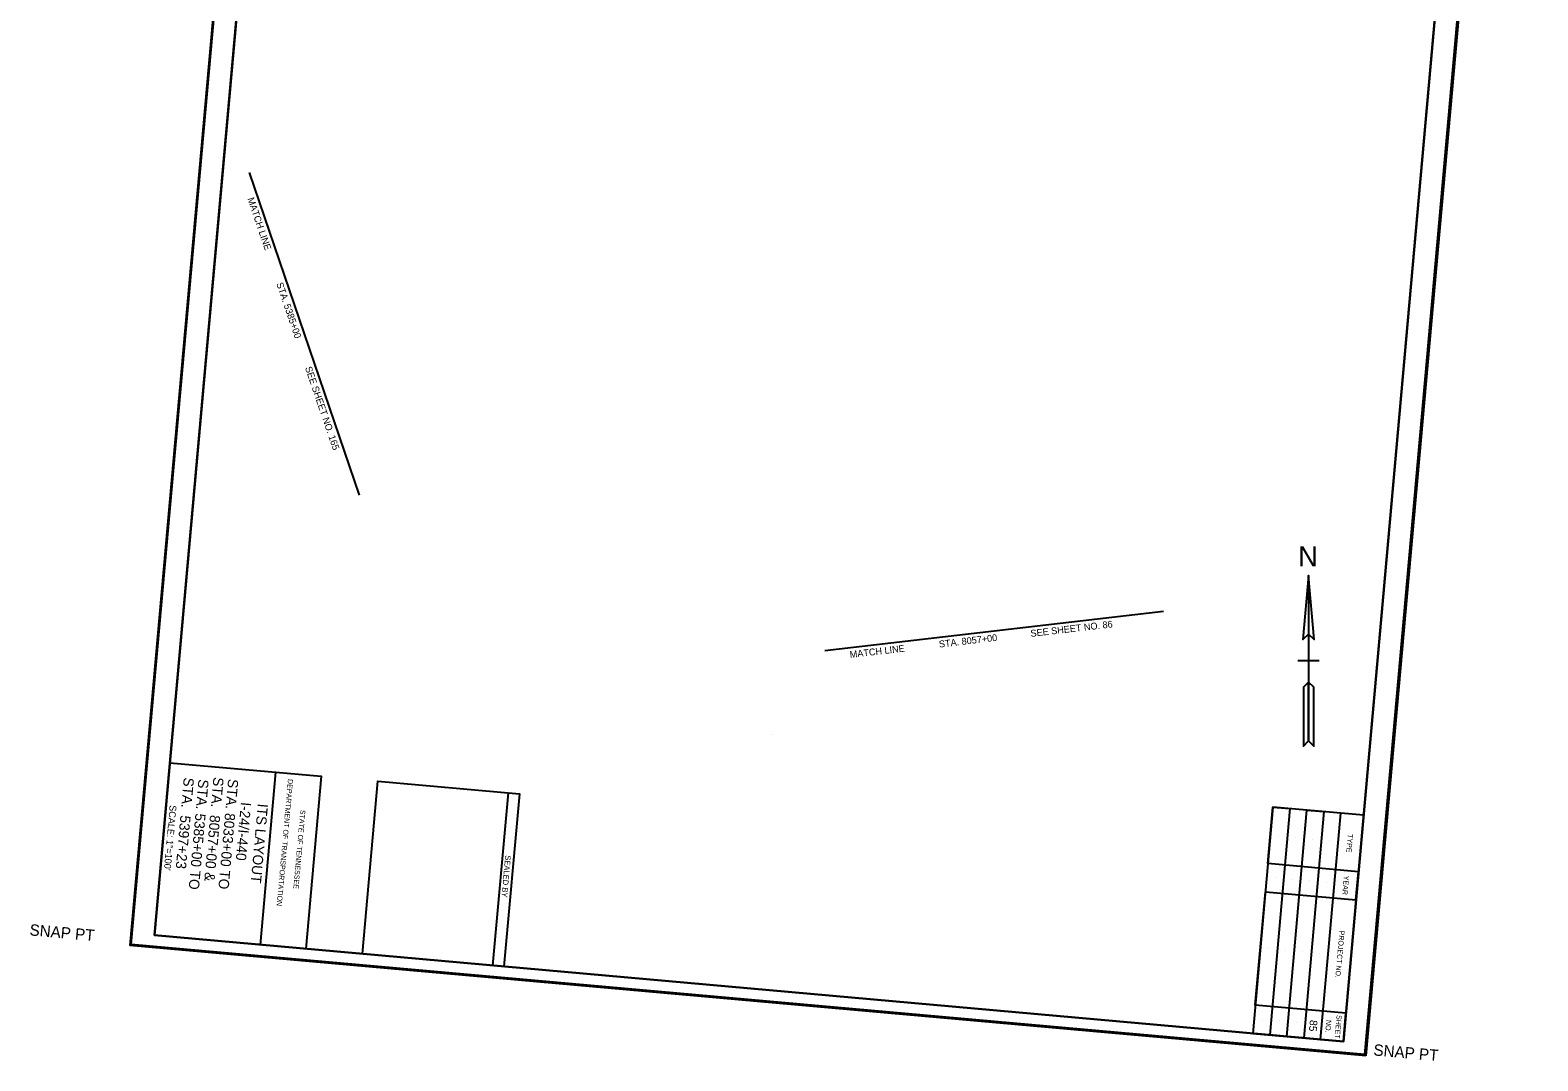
# Model space of a CAD drawing. Extents: x 1751939 to 1754719, y 651993 to 655620.
# Drawn here: x 1751939 to 1754592, y 651993 to 653806 of the extents above; entities that cross this region are included whole.
import ezdxf

# ---------------------------------------------------------------- set-up
doc = ezdxf.new("R2010")
doc.units = 0
for name, color, linetype in [('DESIGN - CENTERLINE - Proposed Text', 7, 'Continuous'), ('DESIGN - SCRATCH - User 1', 7, 'Continuous'), ('DESIGN - SHEET - Corner Text', 7, 'Continuous'), ('DESIGN - SHEET - Linework', 7, 'Continuous'), ('DESIGN - SHEET - Plot Shape', 7, 'Continuous'), ('ITS - CONST TEXT', 7, 'Continuous'), ('ITS - EXISTING COMM CABLE', 7, 'Continuous'), ('ITS - EXISTING HAR', 7, 'Continuous')]:
    doc.layers.add(name, color=color, linetype=linetype)

msp = doc.modelspace()

# ---------------------------------------------------------------- linework, layer by layer
at = {"layer": 'DESIGN - CENTERLINE - Proposed Text'}
for p, q in [((1754188.3, 652696.6), (1754169.4, 652696.6)), ((1754207.2, 652696.6), (1754188.3, 652696.6))]:
    msp.add_line(p, q, dxfattribs=at)
msp.add_lwpolyline([(1754188.3, 652846.6), (1754178.5, 652734), (1754188.3, 652743.8), (1754198.1, 652734), (1754188.3, 652846.6), (1754188.3, 652555.7), (1754197.4, 652546.6), (1754197.4, 652650.1), (1754188.3, 652659.2), (1754179.2, 652650.1), (1754179.2, 652546.6), (1754188.3, 652555.7)], dxfattribs=at)
for points in [[(1754188.3, 652743.8), (1754198.1, 652734), (1754188.3, 652846.6)], [(1754179.2, 652546.6), (1754188.3, 652555.7), (1754188.3, 652659.2), (1754179.2, 652650.1)]]:
    msp.add_lwpolyline(points, close=True, dxfattribs=at)
at = {"layer": 'DESIGN - SCRATCH - User 1'}
for p, q in [((1753243.6, 652566.8), (1753243.6, 652566.8)), ((1754136.2, 652388.3), (1754136.2, 652388.3)), ((1754136.2, 652388.3), (1754136.2, 652388.3)), ((1754136.2, 652388.3), (1754136.2, 652388.3)), ((1754136.2, 652388.3), (1754136.2, 652388.3)), ((1754166.1, 652385.6), (1754166.1, 652385.6)), ((1754166.1, 652385.6), (1754166.1, 652385.6)), ((1754166.1, 652385.6), (1754166.1, 652385.6)), ((1754196, 652383), (1754196, 652383)), ((1754196, 652383), (1754196, 652383)), ((1754225.8, 652380.3), (1754225.8, 652380.3)), ((1752264.5, 652357.1), (1752264.5, 652357.1)), ((1752264.5, 652357.1), (1752264.5, 652357.1)), ((1752264.6, 652357.2), (1752264.6, 652357.2)), ((1754129.6, 652314.6), (1754129.6, 652314.6)), ((1754129.6, 652314.6), (1754129.6, 652314.6)), ((1754129.6, 652314.6), (1754129.6, 652314.6)), ((1754129.6, 652314.6), (1754129.6, 652314.6)), ((1754159.5, 652311.9), (1754159.5, 652311.9)), ((1754159.5, 652311.9), (1754159.5, 652311.9)), ((1754159.5, 652311.9), (1754159.5, 652311.9)), ((1754189.4, 652309.3), (1754189.4, 652309.3)), ((1754189.4, 652309.3), (1754189.4, 652309.3)), ((1754219.3, 652306.6), (1754219.3, 652306.6)), ((1754118.5, 652190.1), (1754118.5, 652190.1)), ((1754118.5, 652190.1), (1754118.5, 652190.1)), ((1754118.5, 652190.1), (1754118.5, 652190.1)), ((1754118.5, 652190.1), (1754118.5, 652190.1)), ((1754148.4, 652187.4), (1754148.4, 652187.4)), ((1754148.4, 652187.4), (1754148.4, 652187.4)), ((1754148.4, 652187.4), (1754148.4, 652187.4)), ((1754178.3, 652184.8), (1754178.3, 652184.8)), ((1754178.3, 652184.8), (1754178.3, 652184.8)), ((1754208.1, 652182.1), (1754208.1, 652182.1)), ((1754107.4, 652065.6), (1754107.4, 652065.6)), ((1754107.4, 652065.6), (1754107.4, 652065.6)), ((1754107.4, 652065.6), (1754107.4, 652065.6)), ((1754107.4, 652065.6), (1754107.4, 652065.6)), ((1754137.3, 652062.9), (1754137.3, 652062.9)), ((1754137.3, 652062.9), (1754137.3, 652062.9)), ((1754137.3, 652062.9), (1754137.3, 652062.9)), ((1754167.1, 652060.3), (1754167.1, 652060.3)), ((1754167.1, 652060.3), (1754167.1, 652060.3)), ((1754197, 652057.6), (1754197, 652057.6))]:
    msp.add_line(p, q, dxfattribs=at)
at = {"layer": 'DESIGN - SHEET - Linework'}
for p, q in [((1752417.5, 655586.2), (1752114.6, 652195.7)), ((1754591.7, 655392), (1754288.8, 652001.5)), ((1752779.9, 652464.3), (1752752.7, 652160.5)), ((1754288.8, 652001.5), (1752114.6, 652195.7))]:
    msp.add_line(p, q, dxfattribs=at)
for points in [[(1754529.6, 655162.7), (1752438, 655349.6), (1752157.8, 652213.7), (1754249.5, 652026.8), (1754529.6, 655162.7)], [(1752185, 652517.4), (1752451.2, 652493.7), (1752424.1, 652189.9), (1752344.4, 652197), (1752371.5, 652500.8)], [(1754285.1, 652425.2), (1754125.7, 652439.4), (1754090.1, 652041), (1754249.5, 652026.8), (1754253.9, 652076.6), (1754094.6, 652090.8), (1754112.4, 652290), (1754271.7, 652275.8), (1754276.2, 652325.6), (1754116.8, 652339.8), (1754125.7, 652439.4), (1754155.6, 652436.8), (1754120, 652038.4), (1754149.9, 652035.7), (1754185.5, 652434.1), (1754215.4, 652431.4), (1754179.8, 652033), (1754209.6, 652030.3), (1754245.2, 652428.8)]]:
    msp.add_lwpolyline(points, dxfattribs=at)
msp.add_lwpolyline([(1752523.7, 652181), (1752550.8, 652484.8), (1752799.8, 652462.5), (1752772.7, 652158.7)], close=True, dxfattribs=at)
at = {"layer": 'DESIGN - SHEET - Plot Shape'}
for points in [[(1754589.5, 655390.2), (1754287, 652003.7), (1752116.8, 652197.5), (1752419.4, 655584.1)], [(1754544.8, 655332.1), (1754249.5, 652026.8), (1752157.8, 652213.7), (1752453.1, 655519)]]:
    msp.add_lwpolyline(points, close=True, dxfattribs=at)
at = {"layer": 'ITS - EXISTING COMM CABLE'}
for p, q in [((1752324.5, 653555.8), (1752518, 652987.9)), ((1753337.4, 652714.5), (1753933.3, 652784.1))]:
    msp.add_line(p, q, dxfattribs=at)

# ---------------------------------------------------------------- texts
at = {"layer": 'DESIGN - CENTERLINE - Proposed Text'}
msp.add_text('N', height=35.4, dxfattribs=at).set_placement((1754170.2, 652862.7))
at = {"layer": 'DESIGN - SHEET - Corner Text'}
for s, height, rotation, p in [('DEPARTMENT OF TRANSPORTATION', 9, 264.8949, (1752392.8, 652489)), ('STATE OF TENNESSEE', 9, 264.8949, (1752414.6, 652434.7)), ('TYPE', 9, 264.8949, (1754257.6, 652392.1)), ('SEALED BY', 10, 264.8949, (1752775.1, 652354.8)), ('YEAR', 9, 264.8949, (1754250.7, 652318.8)), ('SNAP PT  ', 20, 354.8949, (1751937.5, 652213.6)), ('PROJECT NO.', 9, 264.8949, (1754242.8, 652222.2)), ('SHEET', 9, 264.8949, (1754237.9, 652073.7)), ('85', 13.5, 264.8949, (1754190.7, 652065.1)), ('NO.', 9, 264.8949, (1754219.7, 652065)), ('  SNAP PT', 20, 354.8949, (1754287, 652003.7))]:
    msp.add_text(s, height=height, rotation=rotation, dxfattribs=at).set_placement(p)
at = {"layer": 'ITS - CONST TEXT'}
msp.add_text('SCALE: 1"=100\'', height=12, rotation=264.895, dxfattribs=at).set_placement((1752184.8, 652443.1))
at = {"layer": 'ITS - EXISTING COMM CABLE'}
for s, rotation, p in [('MATCH LINE', 288.8171, (1752321.2, 653509.7)), ('STA. 5385+00', 288.8171, (1752372.1, 653360.2)), ('SEE SHEET NO. 165 ', 288.8171, (1752422.6, 653212.2)), ('SEE SHEET NO. 86 ', 6.6592, (1753699.8, 652738.7)), ('STA. 8057+00', 6.6592, (1753538.7, 652719.9)), ('MATCH LINE', 6.6592, (1753381.8, 652701.6))]:
    msp.add_text(s, height=12, rotation=rotation, dxfattribs=at).set_placement(p)
at = {"layer": 'ITS - EXISTING HAR'}
for s, p in [('STA.  5397+23', (1752209.6, 652491.9)), ('STA. 5385+00 TO', (1752235.4, 652488.7)), ('STA.  8057+00 &', (1752261.8, 652492.5)), ('STA. 8033+00 TO', (1752287.6, 652489.3)), ('I-24/I-440', (1752310.1, 652448.5)), ('ITS LAYOUT', (1752339.8, 652445.8))]:
    msp.add_text(s, height=18, rotation=264.895, dxfattribs=at).set_placement(p)

doc.saveas('drawing.dxf')
